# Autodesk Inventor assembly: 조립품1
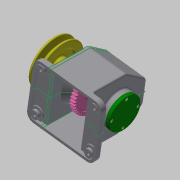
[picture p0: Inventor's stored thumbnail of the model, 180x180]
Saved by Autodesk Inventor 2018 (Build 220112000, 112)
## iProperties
Created: 2022-12
Part Number: 조립품1
Material: 일반
Document SubType Name: Assembly
Designer: home
Author: home
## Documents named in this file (15)
- C:\Users\home\Documents\Inventor\721206V1017\조립품1.iam
- C:\Users\home\Documents\Inventor\721206V1017\본체.ipt
- C:\Users\home\Desktop\721206V1017\뒤커버.ipt
- C:\Users\home\Desktop\721206V1017\앞커버.ipt
- C:\Users\home\Desktop\721206V1017\축.ipt
- C:\Users\home\Desktop\721206V1017\베어링 6203.ipt
- C:\Users\home\Desktop\721206V1017\칼라.ipt
- C:\Users\home\Desktop\721206V1017\오일 실 17 x 32 x 8.ipt
- C:\Users\home\Desktop\721206V1017\V-벨트풀리.ipt
- C:\Users\home\Desktop\721206V1017\멈춤나사 - M4x10.ipt
- C:\Users\home\Desktop\721206V1017\키 - 5 x 5 x 18.ipt
- C:\Users\home\Desktop\721206V1017\키 - 6 x 6 x 22.ipt
- C:\Users\home\Desktop\721206V1017\볼트 M3 x 8.ipt
- C:\Users\home\Desktop\721206V1017\볼트 M3 x 10.ipt
- C:\Users\home\Desktop\721206V1017\스퍼기어.ipt
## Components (9 placed, 3 different names)
1. V-벨트풀리:1
2. ISO 4762 M3 x 10:1
3. ISO 4762 M3 x 10:2
4. ISO 4762 M3 x 10:3
5. ISO 4762 M3 x 10:4
6. ISO 4762 M3 x 8:1
7. ISO 4762 M3 x 8:2
8. ISO 4762 M3 x 8:3
9. ISO 4762 M3 x 8:4
